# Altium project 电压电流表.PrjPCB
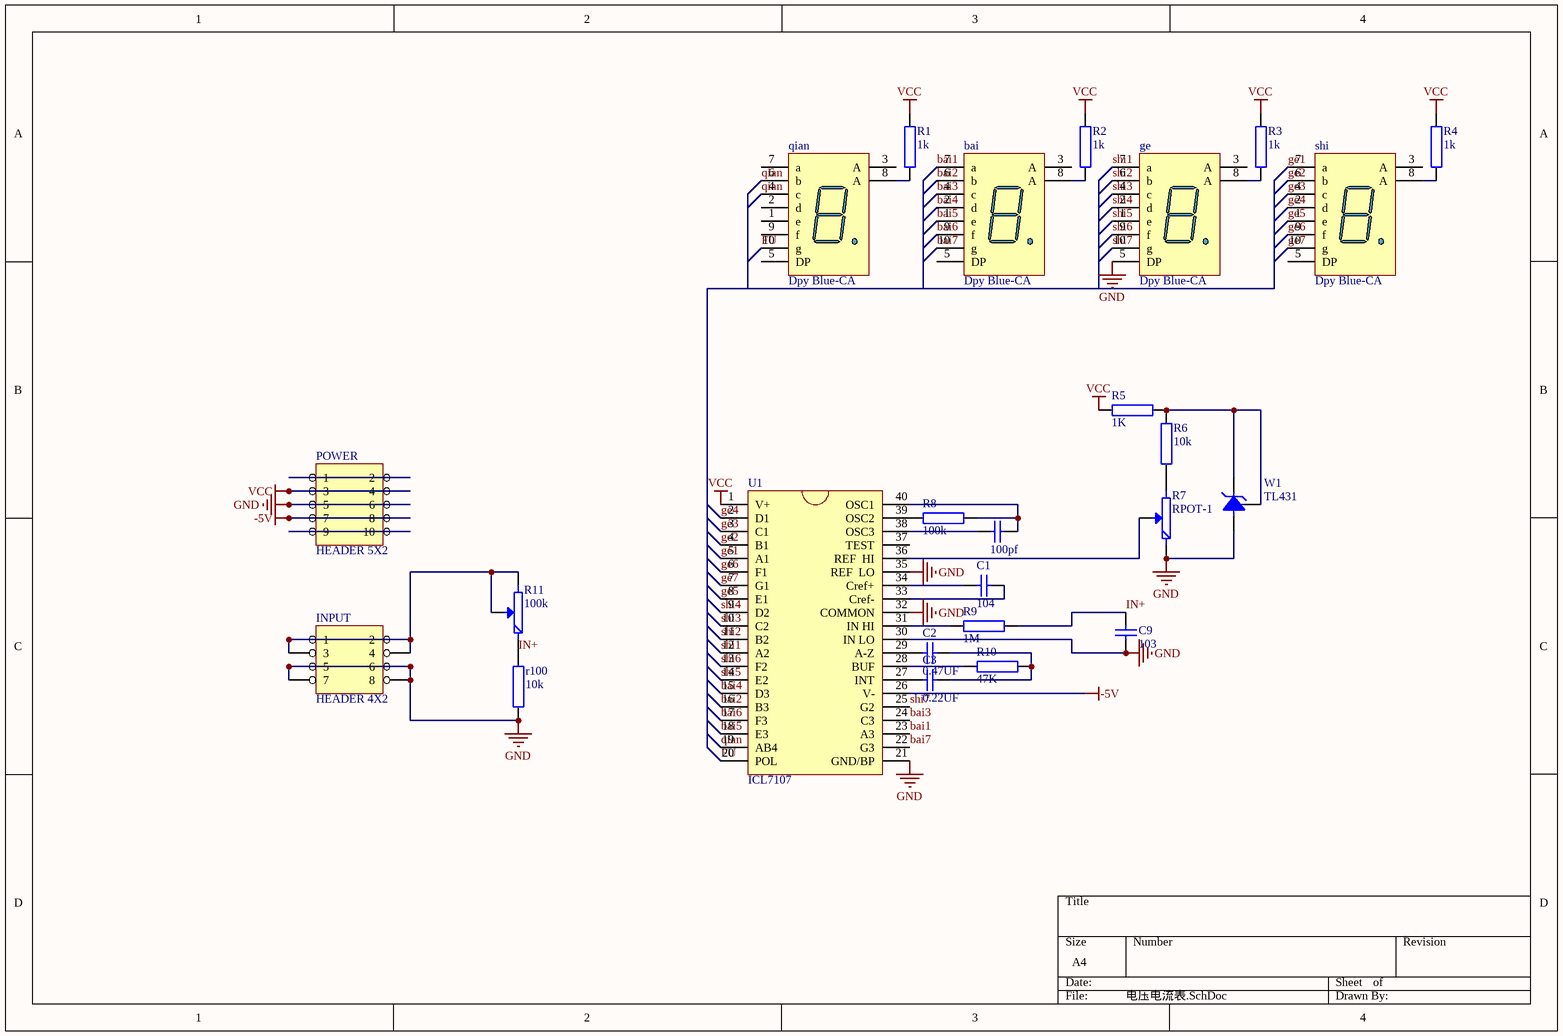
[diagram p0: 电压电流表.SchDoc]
1 sheet, 25 parts. Net scope: global (net labels, ports and power ports of the same name join across sheets).
Board file: 电压电流表.PcbDoc

## Sheet 电压电流表.SchDoc
size A4; PageSetup: Record=PageOptions|CenterHorizontal=True|CenterVertical=True|PrintScale=1.00|XCorrection=1.00|YCorrection=1.00|PrintKind=1|BorderSize=5000000|LeftOffset=0|BottomOffset=0|Orientation=1|PaperLength=1000|PaperWidth=1000|Scale=100|PaperSource=7|PrintQuality=-4|MediaType=1|DitherType=10|PaperKind=A4|PrintScaleMode=1

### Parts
bai  Dpy Blue-CA  [LEDDIP-10/C15.24RHD]
C1  104  [CAP2]
C2  0.47UF  [CAP2]
C3  0.22UF  [CAP2]
C9  103  [CAP2]
ge  Dpy Blue-CA  [LEDDIP-10/C15.24RHD]
INPUT  HEADER 4X2  [IDC-8]
POWER  HEADER 5X2  [IDC-10]
qian  Dpy Blue-CA  [LEDDIP-10/C15.24RHD]
R1  1k  [AXIAL0.3]
R2  1k  [AXIAL0.3]
R3  1k  [AXIAL0.3]
R4  1k  [AXIAL0.3]
R5  1K  [AXIAL0.3]
R6  10k  [AXIAL0.3]
R7  RPOT-1  [RVR-4]
R8  100k  [AXIAL0.3]
R9  1M  [AXIAL0.3]
R10  47K  [AXIAL0.3]
R11  100k  [RVR-4]
r100  10k  [AXIAL0.4]
shi  Dpy Blue-CA  [LEDDIP-10/C15.24RHD]
U1  ICL7107  [PDIP-40]
W1  TL431  [TO-92]
  100pf  [CAP2]

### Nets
-5V: POWER.7 POWER.8 U1.26(V-)
GND: C9.1 ge.5(DP) INPUT.5 INPUT.6 INPUT.7 INPUT.8 POWER.5 POWER.6 R7.1 r100.1 U1.21(GND/BP) U1.30(IN_LO) U1.32(COMMON) U1.35(REF__LO) W1.2(ANODE)
VCC: POWER.3 POWER.4 R1.2 R2.2 R3.2 R4.2 R5.2 U1.1(V+)
bai1: bai.7(a) U1.23(A3)
bai2: bai.6(b) U1.16(B3)
bai3: bai.4(c) U1.24(C3)
bai4: bai.2(d) U1.15(D3)
bai5: bai.1(e) U1.18(E3)
bai6: bai.9(f) U1.17(F3)
bai7: bai.10(g) U1.22(G3)
FU: qian.10(g) U1.20(POL)
ge1: shi.7(a) U1.5(A1)
ge2: shi.6(b) U1.4(B1)
ge3: shi.4(c) U1.3(C1)
ge4: shi.2(d) U1.2(D1)
ge5: shi.1(e) U1.8(E1)
ge6: shi.9(f) U1.6(F1)
ge7: shi.10(g) U1.7(G1)
IN+: C9.2 R9.2 R11.1 r100.2
qian: qian.4(c) qian.6(b) U1.19(AB4)
shi1: ge.7(a) U1.12(A2)
shi2: ge.6(b) U1.11(B2)
shi3: ge.4(c) U1.10(C2)
shi4: ge.2(d) U1.9(D2)
shi5: ge.1(e) U1.14(E2)
shi6: ge.9(f) U1.13(F2)
shi7: ge.10(g) U1.25(G2)
Netbai_8: bai.8(A) R2.1
NetC1_1: C1.1 U1.34(Cref+)
NetC1_2: C1.2 U1.33(Cref-)
NetC2_1: C2.1 U1.29(A-Z)
NetC2_2: C2.2 C3.2 R10.2
NetC3_1: C3.1 U1.27(INT)
Netge_8: ge.8(A) R3.1
NetINPUT_1: INPUT.1 INPUT.2 INPUT.3 INPUT.4 R11.2(M) R11.3
NetPOWER_1: POWER.1 POWER.2
NetPOWER_9: POWER.9 POWER.10
Netqian_8: qian.8(A) R1.1
NetR4_1: R4.1 shi.8(A)
NetR5_1: R5.1 R6.2 W1.1(ref) W1.3(CATHODE)
NetR6_1: R6.1 R7.3
NetR7_2: R7.2(M) U1.36(REF__HI)
NetR8_1: R8.1 U1.39(OSC2)
NetR8_2: R8.2 U1.40(OSC1) .2
NetR9_1: R9.1 U1.31(IN_HI)
NetR10_1: R10.1 U1.28(BUF)
NetU1_38: U1.38(OSC3) .1

Not connected (* = marked no-connect by the designer): bai 3(A) 5(DP); ge 3(A); qian 1(e) 2(d) 3(A) 5(DP) 7(a) 9(f); shi 3(A) 5(DP); U1 37(TEST)

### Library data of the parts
bai ge qian shi = Dpy Blue-CA: 14.2 mm General Purpose Blue 7-Segment Display: CA, RH DP, Gray Surface; MinimumIntensity: 2020 ucd; Note: IF = 10 mA
C1-C3 C9  = Cap: Capacitor
R1-R6 R8-R10 r100 = RES
R7 R11 = RPOT-1: Potentiometer
U1 = ICL7107: 3位半AD转换，可直接驱动LED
